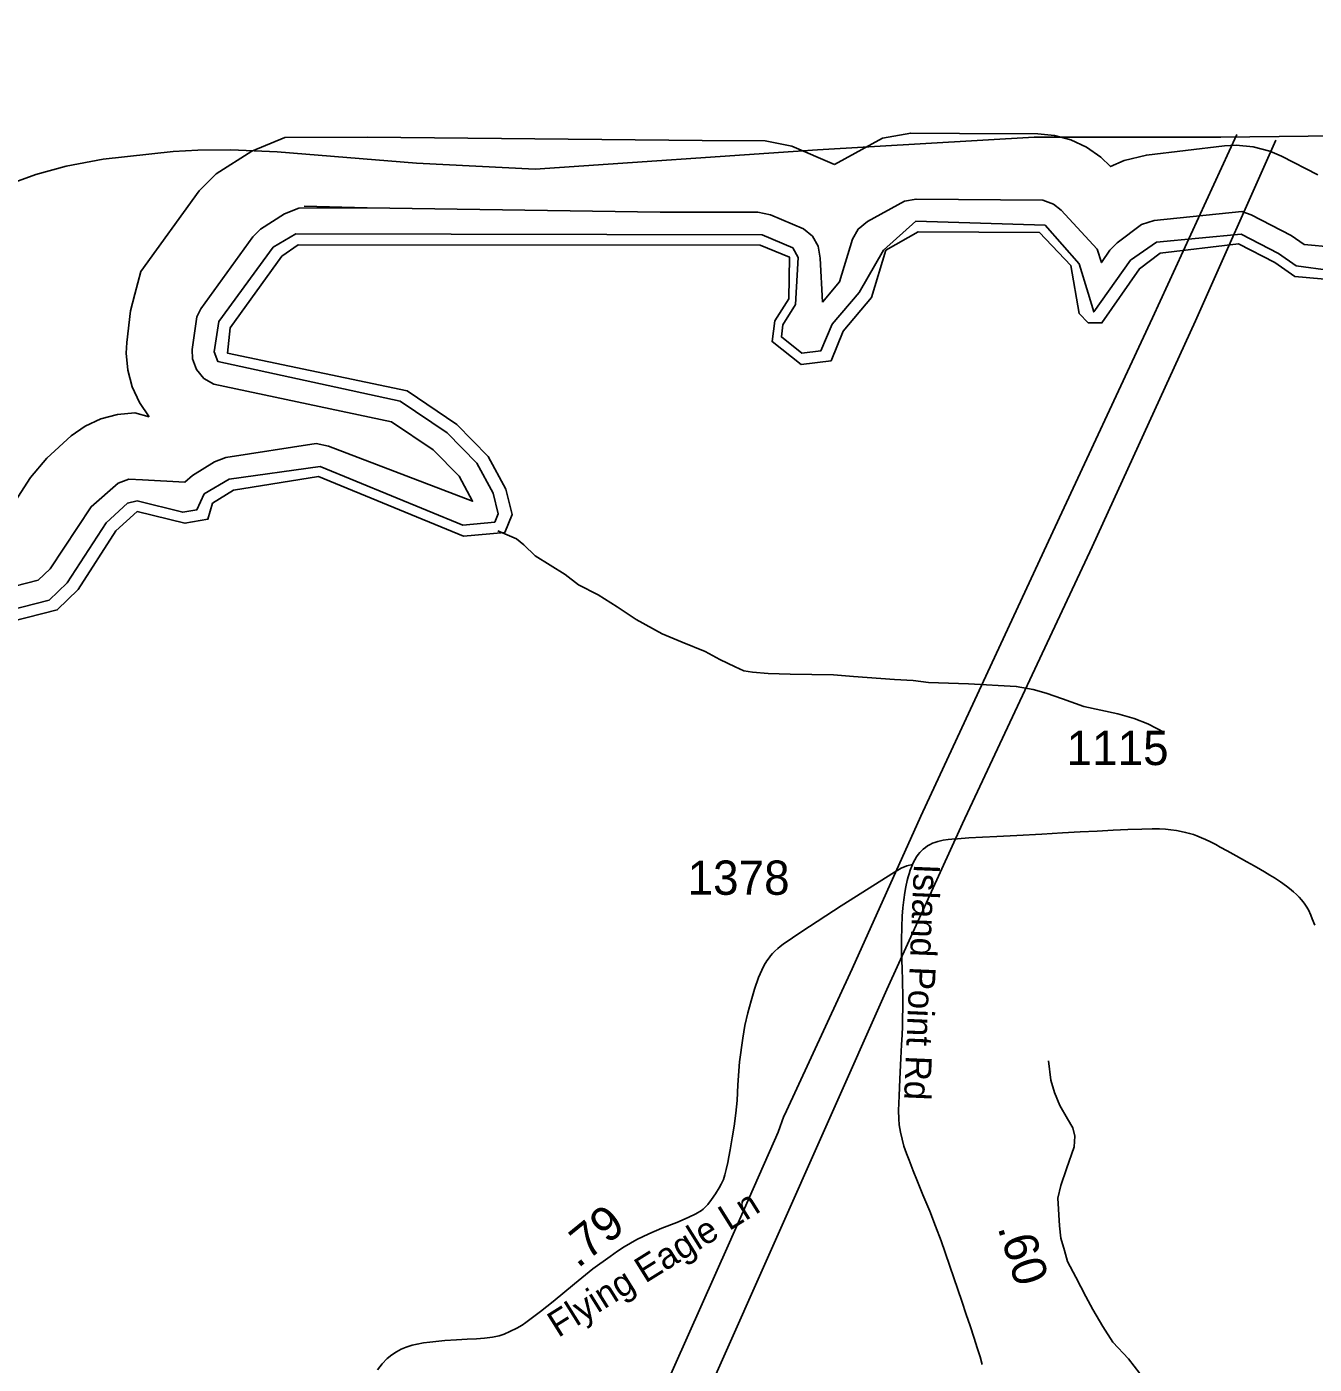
# Model space of a CAD drawing. Extents: x 1383679 to 1536984, y 460658 to 651027.
# Drawn here: x 1388989 to 1393681, y 510693 to 515569 of the extents above; entities that cross this region are included whole.
import ezdxf

# ---------------------------------------------------------------- set-up
doc = ezdxf.new("R2010")
doc.units = 0
for name, color, linetype in [('Exist Boundary Political CountyLine', 7, 'Continuous'), ('Exist Boundary Political StateLine', 7, 'Continuous'), ('Exist Hydrographic Bay Label', 7, 'Continuous'), ('Exist Hydrographic Buffer Line', 7, 'Continuous'), ('Exist Hydrographic Misc Water Feature', 7, 'Continuous'), ('Exist Road Secondary Mileage Hundredths English Label', 7, 'Continuous'), ('Exist Road Secondary Type 51 Attributed', 7, 'Continuous'), ('Exist Road Secondary Type 51 Label', 7, 'Continuous'), ('Exist Road Secondary Type 51 Number Label', 7, 'Continuous'), ('Exist Utilities Electrical Transmission Line', 7, 'Continuous')]:
    doc.layers.add(name, color=color, linetype=linetype)

msp = doc.modelspace()

# ---------------------------------------------------------------- linework, layer by layer
at = {"layer": 'Exist Boundary Political CountyLine'}
msp.add_lwpolyline([(1391870.9, 515120.1), (1392660.8, 515167.1), (1393341.2, 515167.1), (1394084.1, 515174.9), (1394529.9, 515214), (1394811.4, 515284.4), (1395319.3, 515508.7), (1395767.8, 515811.4)], dxfattribs=at)
at = {"layer": 'Exist Boundary Political StateLine'}
msp.add_lwpolyline([(1388905.5, 514987.4), (1389022.4, 515030.9), (1389133, 515060.7), (1389267.6, 515086), (1389522.3, 515114.7), (1389612.4, 515118.7), (1389732.5, 515120.2), (1389902.4, 515112.8), (1390409.8, 515072.2), (1390841.6, 515049.3), (1391870.9, 515120.1)], dxfattribs=at)
at = {"layer": 'Exist Hydrographic Bay Label'}
for points in [[(1390556.5, 514119.5), (1390375.4, 514241.3), (1389720.5, 514379.2), (1389730.5, 514470.8), (1389919.5, 514732.9), (1389978.5, 514774.4), (1391662.4, 514773.4), (1391769.3, 514728.6), (1391766.4, 514577.7), (1391715.4, 514496.7), (1391705.4, 514421.3), (1391811.4, 514337.1), (1391920.4, 514351.4), (1391964.4, 514458.8), (1392067.4, 514581.5), (1392120.4, 514754.4), (1392238.4, 514821), (1392680.4, 514818.6), (1392794.4, 514698.2), (1392824.3, 514523.7), (1392857.3, 514490.1), (1392907.4, 514489.2), (1393044.3, 514686.6), (1393120.3, 514744.1), (1393405.3, 514777.8), (1393537.4, 514709.6), (1393610.4, 514658.8), (1393844.3, 514637.7)], [(1388647.5, 513327.3), (1389100.4, 513443), (1389176.5, 513516.9), (1389314.5, 513730.8), (1389391.5, 513801.5), (1389565.5, 513758.6), (1389649.5, 513773.4), (1389666.5, 513832.1), (1389742.4, 513879.8), (1390052.5, 513929.4), (1390581.4, 513712), (1390731.4, 513725.4), (1390758.5, 513790.4), (1390735.4, 513882.8), (1390671.4, 514002.3), (1390556.5, 514119.5)]]:
    msp.add_lwpolyline(points, dxfattribs=at)
at = {"layer": 'Exist Hydrographic Buffer Line'}
for points in [[(1391451, 515153.9), (1390231.6, 515166.6), (1389929.3, 515165.2), (1389809.2, 515116.1), (1389679.6, 515032.5), (1389617.2, 514970.8), (1389405.1, 514676.8)], [(1392388.1, 515179.7), (1392210.6, 515181.4), (1392107.9, 515163.5), (1391933.3, 515067.5)], [(1393693.9, 515029), (1393561.8, 515097.2), (1393519.7, 515115.7), (1393459.1, 515131.9), (1393396.6, 515137.4), (1393354.4, 515134.9), (1393069.4, 515101.3), (1392988.4, 515082.1), (1392939.3, 515059.2), (1392903, 515094.1), (1392851.6, 515130), (1392794.7, 515156.6), (1392734.2, 515172.8), (1392673.6, 515178.2), (1392388.1, 515179.7)], [(1391933.3, 515067.5), (1391777.8, 515134), (1391679.8, 515153.7), (1391451, 515153.9)], [(1393856.4, 514755.5), (1393644.1, 514775.1), (1393597.1, 514807.7), (1393451.6, 514884), (1393417.4, 514895.6), (1393097.5, 514863), (1393051.6, 514847.7), (1392963.1, 514781.9), (1392936.9, 514754.6), (1392905.5, 514709.1), (1392889.6, 514757.8), (1392758.8, 514900.8), (1392731.6, 514922.2), (1392692.4, 514936.4), (1392230.2, 514940.6), (1392188.6, 514933.4), (1392052.7, 514858.6), (1392019.6, 514831.2), (1391998.8, 514795.1), (1391951.1, 514639.7), (1391888.8, 514565.5)], [(1390000.7, 514914.9), (1390230.3, 514909.3), (1391298.1, 514893.3), (1390230.3, 514909.3), (1389980.4, 514908.1), (1389928.6, 514887), (1389841.6, 514830.8), (1389813.4, 514802.9), (1389624.3, 514540.8), (1389608.9, 514511.7), (1389592.3, 514391.9), (1389593.5, 514358.1), (1389607.7, 514319), (1389634.6, 514287), (1389670.7, 514266.2), (1390319, 514128.4), (1390470.6, 514026.5), (1390564.9, 513930.2), (1390613.8, 513839), (1390089.3, 514040.1), (1390043.7, 514049.1), (1389714.7, 513998.1), (1389673.6, 513983.4), (1389593.8, 513933.4), (1389565.7, 513909), (1389411.4, 513917.8), (1389361.9, 513919.4), (1389322.7, 513905.2), (1389224.5, 513818.9), (1389074.3, 513593.2), (1389030.9, 513551.1), (1388608.9, 513443.4)], [(1391888.8, 514565.5), (1391880.5, 514725.9), (1391873.3, 514769.4), (1391852.5, 514805.5), (1391820.5, 514832.2), (1391700, 514883.8), (1391653.7, 514893.1), (1391298.1, 514893.3)], [(1392700.6, 514845.7), (1392229.8, 514860.6), (1392111.6, 514754.1)], [(1393865.9, 514663.4), (1393615.8, 514697.3), (1393551.5, 514742), (1393414.9, 514812.9), (1393106.8, 514783.5), (1393011.4, 514718.1), (1392878, 514529.2), (1392857.2, 514598.3), (1392825.1, 514704.6), (1392700.6, 514845.7)], [(1392111.6, 514754.1), (1392022.7, 514600.7), (1391924.9, 514484.2), (1391883.4, 514387.7), (1391814.2, 514378.7), (1391739.2, 514438.3), (1391745.1, 514482.4), (1391791.4, 514556.1), (1391800.6, 514727.5), (1391780.6, 514763), (1391669.1, 514810), (1389969.6, 514814.2), (1389887.6, 514765.4), (1389689.2, 514494), (1389671.9, 514383.3), (1389686, 514348.3), (1390350.7, 514203.5), (1390521.9, 514088.3), (1390630, 513978.1), (1390689, 513868), (1390707.6, 513793.3), (1390694.9, 513762.8), (1390578.7, 513752.4), (1390058.8, 513966.1), (1389727.3, 513919.1), (1389636.3, 513865.7), (1389609.2, 513808.2), (1389558.1, 513799.2), (1389392.2, 513840.1), (1389356.9, 513831.9), (1389278.6, 513760), (1389136.5, 513542.2), (1389071.4, 513478.9), (1388628.7, 513365.9)], [(1389405.1, 514676.8), (1389383.3, 514593.7), (1389367.1, 514533.1), (1389353.8, 514417.8), (1389351.7, 514378.9), (1389357.1, 514316.5), (1389373.3, 514255.8), (1389399.9, 514199), (1389435.9, 514147.5)], [(1389435.9, 514147.5), (1389382.7, 514161.3), (1389320.1, 514155.8), (1389259.5, 514139.5), (1389202.6, 514113), (1389151.3, 514077.1), (1389062.2, 513995.8), (1389003.2, 513925.8), (1388899.7, 513765.3), (1388549.6, 513675.9), (1388439.1, 513626.8), (1388329.1, 513553.5), (1388297.2, 513529.7), (1388252.8, 513485.3), (1388219.8, 513438.9), (1388119.9, 513272)]]:
    msp.add_lwpolyline(points, dxfattribs=at)
at = {"layer": 'Exist Hydrographic Misc Water Feature'}
for points in [[(1390706.2, 513731.1), (1390773.6, 513701.9), (1390801.2, 513680.8), (1390842.3, 513640.6), (1390951, 513571.9), (1391000.2, 513534.8), (1391071.5, 513497.3), (1391140.7, 513454.1), (1391209.7, 513408.3), (1391304.6, 513356.3), (1391378, 513325.3), (1391461.4, 513291.7), (1391514.8, 513261.9), (1391570.4, 513235.3), (1391602.1, 513220.8), (1391633.9, 513216), (1391691.8, 513210.7), (1391771.8, 513209.1), (1391929.8, 513205.9), (1392001.8, 513200.4), (1392151.6, 513189.2), (1392219.6, 513185.3), (1392275.5, 513178.5), (1392421.3, 513173.1), (1392595.2, 513163.9), (1392657.1, 513152.7), (1392704.8, 513139.5), (1392764.4, 513118.6), (1392841.9, 513090.8), (1392965.3, 513063.6), (1393025.1, 513046.9), (1393074.7, 513027.8), (1393136.1, 512996.2)], [(1393045.4, 510659.4), (1393004.5, 510711.8), (1392947.8, 510772.9), (1392910.9, 510830.3), (1392874.2, 510892.5), (1392849.2, 510939), (1392812.7, 511010.3), (1392781.8, 511066.7), (1392770.7, 511107.2), (1392757.5, 511151.7), (1392752.5, 511197.8), (1392746.6, 511298), (1392757.5, 511343.8), (1392778.8, 511404.9), (1392806.5, 511484.7), (1392809.3, 511524.1), (1392802, 511554.6), (1392782.6, 511587), (1392753.6, 511636), (1392734.7, 511683.9), (1392721.5, 511728.5), (1392712.9, 511798.5)]]:
    msp.add_lwpolyline(points, dxfattribs=at)
at = {"layer": 'Exist Road Secondary Type 51 Attributed'}
for points in [[(1393179.1, 512638.9), (1393158.9, 512641.6), (1393139.1, 512643.9), (1393116.9, 512644.8), (1393090.9, 512644.8), (1393052.6, 512644), (1393002.2, 512642.6), (1392948.5, 512640), (1392889.9, 512636.8), (1392827.9, 512633.9), (1392764.1, 512630), (1392689.1, 512625.7), (1392597.9, 512620.3), (1392524.6, 512617.2), (1392472.5, 512614.2), (1392422.9, 512611.6), (1392381, 512608.8), (1392360.1, 512607.5), (1392346.8, 512606.1), (1392328.9, 512603.3), (1392319.5, 512601.2), (1392309.3, 512598.6), (1392298.9, 512595.1), (1392290.4, 512592), (1392281.3, 512587.7), (1392272.4, 512582.8), (1392264, 512577.1), (1392255.7, 512570.4), (1392248.6, 512563.4), (1392244, 512558.4), (1392238.3, 512551.2), (1392232.1, 512542.4), (1392225.9, 512531.9), (1392218.7, 512518.2), (1392217.2, 512514.9)], [(1393683, 512293.7), (1393674.2, 512316.7), (1393668.7, 512330.2), (1393659.9, 512349.1), (1393652, 512362.8), (1393644.7, 512373.4), (1393635.4, 512385.3), (1393626, 512396.1), (1393616.7, 512405.5), (1393606.1, 512415.3), (1393591.6, 512427.1), (1393580.2, 512435.6), (1393558.2, 512451.6), (1393536.8, 512465.9), (1393519.6, 512476.3), (1393500, 512488), (1393485.7, 512496.3), (1393462.2, 512509.7), (1393435.8, 512524.6), (1393396.6, 512546.4), (1393363.4, 512564), (1393338.3, 512578.3), (1393322.3, 512587.2), (1393302.6, 512597.3), (1393285.5, 512605.7), (1393270, 512612.2), (1393253.9, 512618.8), (1393241.5, 512623.5), (1393226.7, 512627.9), (1393212.1, 512631.8), (1393195.8, 512635.5), (1393179.1, 512638.9)], [(1392217.2, 512514.9), (1392197, 512510.3), (1392176.5, 512501.6), (1392151.5, 512487.1), (1391957.6, 512364.4), (1391813.3, 512270.5), (1391746.4, 512223.8), (1391735.5, 512215.8), (1391726.5, 512208.5), (1391715.1, 512198.2), (1391707.6, 512190.5), (1391700.3, 512181.7), (1391694.6, 512173.9), (1391686.7, 512162.9), (1391677.2, 512147.1), (1391667.7, 512129.7), (1391656.2, 512102.5), (1391641.4, 512060.6), (1391629.3, 512017.2), (1391616.8, 511973.9), (1391606.5, 511927.5), (1391598.6, 511881.2), (1391586.2, 511795.7), (1391580.8, 511711.3), (1391578.4, 511654.4), (1391573.8, 511607.6), (1391567.3, 511560.3), (1391560.3, 511518.1), (1391552.6, 511474.5), (1391548.1, 511448.7), (1391543.8, 511428), (1391538.6, 511402.2), (1391533.6, 511382.9), (1391528, 511366.7), (1391520.1, 511348.7), (1391513.1, 511336), (1391499.7, 511313.7), (1391485.1, 511292.9), (1391471, 511275), (1391462.2, 511264.9), (1391454.2, 511257.9), (1391447.7, 511253.1), (1391428, 511241.6), (1391399.2, 511228.1), (1391358.3, 511209.7), (1391303.8, 511188.6), (1391255.8, 511168.3), (1391213.1, 511148), (1391166.7, 511120.4), (1391142.5, 511104.6), (1391115.4, 511085.1), (1391052.8, 511040.5), (1390985.1, 510985.5), (1390907.2, 510921.6), (1390862.1, 510885.3), (1390808.6, 510844.2), (1390795.1, 510835.2), (1390775.2, 510823.8), (1390749.7, 510811.5), (1390729.6, 510802.8), (1390710.8, 510796.7), (1390687.1, 510791.4), (1390657.6, 510787.6), (1390627.8, 510785.2), (1390594.3, 510783.7), (1390554.9, 510782.1), (1390513.1, 510778.9), (1390458.5, 510773.3), (1390435.6, 510770.4), (1390411.5, 510766.4), (1390393.5, 510761.6), (1390372, 510754.6), (1390353.6, 510747.1), (1390336.5, 510737.9), (1390319.3, 510726.9), (1390303.1, 510713.8), (1390284.7, 510693.6), (1390267.7, 510671.8)], [(1392217.2, 512514.9), (1392214.2, 512508.4), (1392208.8, 512493.8), (1392204.6, 512481.2), (1392201.7, 512470.1), (1392198.3, 512455.8), (1392193.5, 512433.8), (1392189.4, 512412.6), (1392185.6, 512385.6), (1392182.4, 512356.5), (1392179.8, 512325.9), (1392178, 512286.9), (1392177, 512239.2), (1392177.6, 512189), (1392179.1, 512137.2), (1392180.7, 512090.5), (1392181.5, 512032.1), (1392181.8, 511988.4), (1392181.3, 511957.8), (1392180.4, 511924.3), (1392179.1, 511893.4), (1392177.2, 511857), (1392175, 511808.3), (1392170.9, 511732.4), (1392168.1, 511671.8), (1392166.5, 511617.3), (1392167.2, 511587.9), (1392169.1, 511565.6), (1392173.7, 511538.6), (1392179.1, 511513.2), (1392186.1, 511488.2), (1392195.2, 511461.5), (1392204.6, 511436.7), (1392220, 511397.2), (1392235.6, 511358.5), (1392255.4, 511310.3), (1392279.8, 511251.2), (1392301.5, 511196), (1392321.3, 511142.1), (1392336, 511100.1), (1392353.2, 511050.8), (1392367.9, 511008.2), (1392382.3, 510965.7), (1392396.6, 510922.6), (1392413.1, 510873.8), (1392427.7, 510832.5), (1392442.3, 510787.5), (1392453.4, 510752.7), (1392463.3, 510719.7), (1392471.2, 510692.1)]]:
    msp.add_lwpolyline(points, dxfattribs=at)
at = {"layer": 'Exist Utilities Electrical Transmission Line'}
for points in [[(1393398.6, 515176.5), (1393091.3, 514508.2), (1392729, 513727.5), (1392247.3, 512691), (1391997.6, 512133.9), (1391750.3, 511600.6), (1391748.2, 511596.9), (1391727.1, 511539.3), (1391550.7, 511136.6), (1391147.6, 510230.5), (1390854.7, 509614.3), (1390401.7, 508613.2), (1390362.9, 508576.1), (1389477.4, 507887.6)], [(1393541.6, 515156.2), (1393249.1, 514497), (1392872, 513672.4), (1392398.8, 512663.9), (1392124.1, 512059.1), (1391500.5, 510655.4), (1391316.2, 510255.2), (1391288.9, 510191.7), (1391079.1, 509727.7), (1390860.8, 509234), (1390483, 508385.4), (1390449.6, 508320.1), (1389738.2, 507671.5)]]:
    msp.add_lwpolyline(points, dxfattribs=at)

# ---------------------------------------------------------------- texts
at = {"layer": 'Exist Road Secondary Mileage Hundredths English Label'}
for s, rotation, p in [('.79', 39.1172, (1390997.8, 511040.2)), ('.60', 287.6257, (1392526.5, 511190.9))]:
    msp.add_text(s, height=125, rotation=rotation, dxfattribs=at).set_placement(p)
at = {"layer": 'Exist Road Secondary Type 51 Label'}
for s, rotation, p in [('Island Point Rd', 267.5756, (1392222.8, 512518)), ('Flying Eagle Ln', 32.0074, (1390926.2, 510787.8))]:
    msp.add_text(s, height=95, rotation=rotation, dxfattribs=at).set_placement(p)
at = {"layer": 'Exist Road Secondary Type 51 Number Label'}
for s, p in [('1115', (1392778.6, 512877.2)), ('1378', (1391397.5, 512404.2))]:
    msp.add_text(s, height=125, dxfattribs=at).set_placement(p)

doc.saveas('drawing.dxf')
